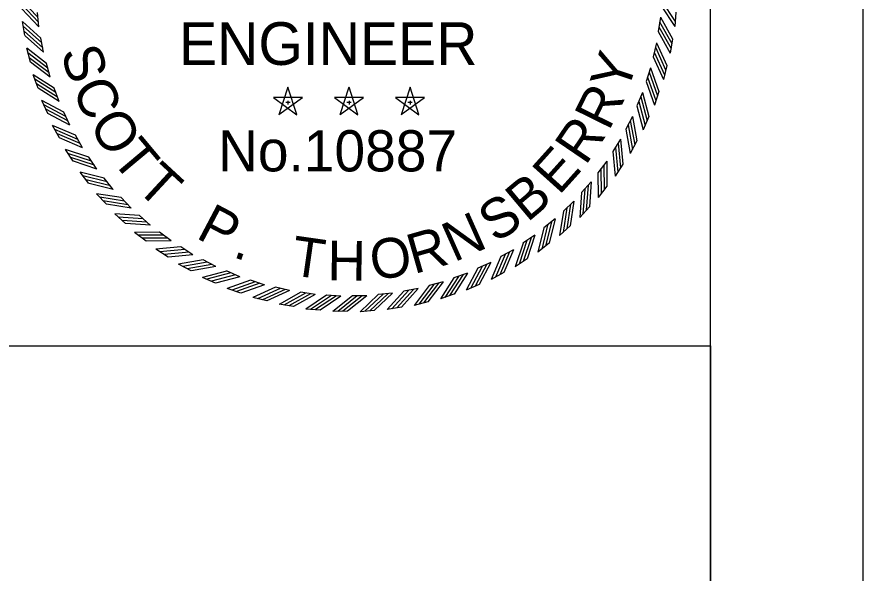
# Model space of a CAD drawing. Extents: x 0 to 1228740, y 0 to 152440.
# Drawn here: x 30.801 to 34, y 16.545 to 18.649 of the extents above; entities that cross this region are included whole.
import ezdxf

# ---------------------------------------------------------------- set-up
doc = ezdxf.new("R2010")
doc.units = 0
for name, color, linetype in [('R_Border', 7, 'Continuous'), ('R_No Plot', 7, 'Continuous'), ('STAMP', 7, 'Continuous')]:
    doc.layers.add(name, color=color, linetype=linetype)

msp = doc.modelspace()

# ---------------------------------------------------------------- linework, layer by layer
at = {"layer": 'R_Border'}
msp.add_line((33.4231, 0.5768), (33.4231, 21.4232), dxfattribs=at)
msp.add_lwpolyline([(33.9999, 22), (0, 22), (0, 0), (33.9999, 0)], close=True, dxfattribs=at)
at = {"layer": 'R_No Plot'}
for points in [[(33.4231, 17.4052), (33.4231, 10.8708), (1.516, 10.8708), (1.516, 21.4232), (25.1971, 21.4232), (25.1971, 20.4352), (28.7491, 20.4352), (28.7491, 20.0782), (29.1131, 20.0782), (29.1131, 20.1432), (30.6665, 20.1432)], [(30.6665, 20.1432), (30.6665, 17.4052), (33.4231, 17.4052)]]:
    msp.add_lwpolyline(points, dxfattribs=at)
at = {"layer": 'STAMP'}
for p, q in [((30.8837, 18.6117), (30.8787, 18.666)), ((33.2925, 18.6677), (33.2885, 18.6135)), ((30.8314, 18.5785), (30.822, 18.6321)), ((33.2337, 18.6484), (33.2252, 18.5945)), ((30.9013, 18.5154), (30.8918, 18.5691)), ((33.2793, 18.566), (33.2708, 18.5123)), ((30.8519, 18.478), (30.8381, 18.5306)), ((33.2191, 18.5516), (33.2062, 18.4986)), ((30.9268, 18.4209), (30.9129, 18.4737)), ((33.2577, 18.4657), (33.2449, 18.4129)), ((30.8807, 18.3796), (30.8626, 18.4309)), ((33.1965, 18.4563), (33.1793, 18.4046)), ((30.96, 18.3289), (30.9419, 18.3803)), ((31.8255, 18.384), (31.7915, 18.2795)), ((31.8594, 18.2796), (31.8256, 18.3841)), ((32.0563, 18.384), (32.0222, 18.2795)), ((32.0902, 18.2796), (32.0564, 18.3841)), ((32.2871, 18.384), (32.253, 18.2795)), ((32.321, 18.2796), (32.2871, 18.3841)), ((33.1662, 18.3633), (33.1447, 18.3131)), ((33.228, 18.3676), (33.2108, 18.316)), ((30.9175, 18.2838), (30.8952, 18.3335)), ((31.8804, 18.3441), (31.7705, 18.3442)), ((31.7706, 18.3441), (31.8594, 18.2795)), ((31.7916, 18.2796), (31.8805, 18.3441)), ((31.8256, 18.3324), (31.8256, 18.3186)), ((32.1112, 18.3441), (32.0013, 18.3442)), ((32.0014, 18.3441), (32.0902, 18.2795)), ((32.0224, 18.2796), (32.1113, 18.3441)), ((32.0564, 18.3324), (32.0564, 18.3186)), ((32.3419, 18.3441), (32.2321, 18.3442)), ((32.2322, 18.3441), (32.321, 18.2795)), ((32.2532, 18.2796), (32.3421, 18.3441)), ((32.2872, 18.3324), (32.2872, 18.3186)), ((31.8177, 18.3266), (31.834, 18.3266)), ((32.0485, 18.3266), (32.0648, 18.3266)), ((32.2793, 18.3266), (32.2956, 18.3266)), ((31.0007, 18.2399), (30.9784, 18.2896)), ((33.1283, 18.273), (33.1027, 18.2248)), ((33.1902, 18.2722), (33.1688, 18.2222)), ((30.9621, 18.1915), (30.9357, 18.2391)), ((31.0487, 18.1545), (31.0223, 18.2022)), ((33.083, 18.1863), (33.0536, 18.1403)), ((33.1447, 18.1803), (33.1192, 18.1323)), ((31.0141, 18.1031), (30.9839, 18.1484)), ((31.1035, 18.0734), (31.0732, 18.1188)), ((33.0308, 18.1035), (32.9977, 18.0601)), ((33.0917, 18.0925), (33.0624, 18.0467)), ((31.0733, 18.0193), (31.0395, 18.062)), ((31.1648, 17.9971), (31.1309, 18.0399)), ((32.9719, 18.0253), (32.9353, 17.9849)), ((31.1392, 17.9407), (31.1019, 17.9804)), ((33.0317, 18.0093), (32.9987, 17.9661)), ((31.2322, 17.9262), (31.1949, 17.966)), ((32.9067, 17.9523), (32.8669, 17.915)), ((32.965, 17.9314), (32.9286, 17.8911)), ((31.2113, 17.8678), (31.1709, 17.9043)), ((31.3052, 17.861), (31.2648, 17.8976)), ((32.8357, 17.8849), (32.793, 17.851)), ((32.8922, 17.8593), (32.8525, 17.8221)), ((31.2892, 17.8012), (31.246, 17.8342)), ((31.3834, 17.8021), (31.34, 17.8352)), ((32.7595, 17.8236), (32.7141, 17.7933)), ((32.8136, 17.7934), (32.7709, 17.7596)), ((31.3724, 17.7411), (31.3266, 17.7705)), ((31.4661, 17.7499), (31.4202, 17.7793)), ((32.6784, 17.7688), (32.6306, 17.7424)), ((31.5529, 17.7046), (31.5047, 17.7301)), ((32.7298, 17.7342), (32.6845, 17.704)), ((31.4602, 17.6882), (31.4121, 17.7136)), ((32.593, 17.7208), (32.5433, 17.6985)), ((31.5521, 17.6427), (31.5021, 17.6641)), ((31.6432, 17.6667), (31.593, 17.6882)), ((32.504, 17.6801), (32.4526, 17.662)), ((32.6414, 17.6822), (32.5938, 17.6558)), ((31.7362, 17.6364), (31.6845, 17.6536)), ((32.4119, 17.6469), (32.3592, 17.633)), ((32.549, 17.6376), (32.4994, 17.6153)), ((31.6475, 17.6049), (31.5959, 17.6221)), ((31.8315, 17.6138), (31.7785, 17.6267)), ((31.9283, 17.5992), (31.8744, 17.6077)), ((32.0259, 17.5927), (31.9715, 17.5967)), ((32.2212, 17.6038), (32.1669, 17.5988)), ((32.3175, 17.6214), (32.2637, 17.6119)), ((32.4533, 17.6008), (32.402, 17.5827)), ((31.7456, 17.5751), (31.6928, 17.588)), ((32.1238, 17.5942), (32.0692, 17.5937)), ((32.3549, 17.572), (32.3023, 17.5582)), ((31.8459, 17.5536), (31.7922, 17.5621)), ((31.9476, 17.5404), (31.8934, 17.5444)), ((32.0501, 17.5356), (31.9957, 17.5351)), ((32.1526, 17.5393), (32.0984, 17.5343)), ((32.2544, 17.5515), (32.2008, 17.5421))]:
    msp.add_line(p, q, dxfattribs=at)
for points in [[(30.8802, 18.6479), (30.8157, 18.7165)], [(30.8823, 18.6291), (30.8178, 18.6977)], [(33.2363, 18.6917), (33.2885, 18.6134)], [(33.2378, 18.7098), (33.29, 18.6315)], [(30.8838, 18.6117), (30.8193, 18.6803)], [(30.8918, 18.5691), (30.8219, 18.6321)], [(33.2307, 18.6312), (33.2764, 18.5488)], [(33.2336, 18.6484), (33.2793, 18.5661)], [(30.8948, 18.5512), (30.8249, 18.6142)], [(30.8985, 18.5327), (30.8286, 18.5957)], [(33.2252, 18.5945), (33.2709, 18.5122)], [(33.2282, 18.6124), (33.2739, 18.5301)], [(30.9014, 18.5154), (30.8315, 18.5784)], [(30.9129, 18.4736), (30.838, 18.5307)], [(33.2147, 18.5347), (33.2534, 18.4489)], [(33.219, 18.5517), (33.2577, 18.4658)], [(30.9174, 18.456), (30.8425, 18.5131)], [(30.9226, 18.4379), (30.8477, 18.4949)], [(33.2062, 18.4986), (33.2449, 18.4128)], [(33.2107, 18.5162), (33.2493, 18.4304)], [(30.9269, 18.4209), (30.852, 18.478)], [(30.9418, 18.3802), (30.8625, 18.4309)], [(33.1908, 18.4398), (33.2223, 18.3511)], [(33.1965, 18.4564), (33.228, 18.3677)], [(30.9477, 18.3631), (30.8684, 18.4138)], [(30.9544, 18.3454), (30.8751, 18.3961)], [(33.1793, 18.4046), (33.2108, 18.3159)], [(33.1852, 18.4218), (33.2167, 18.3331)], [(30.9601, 18.3288), (30.8808, 18.3795)], [(33.1662, 18.3634), (33.1902, 18.2723)], [(30.9784, 18.2895), (30.8951, 18.3335)], [(33.1591, 18.3473), (33.1832, 18.2563)], [(30.9857, 18.2729), (30.9024, 18.3169)], [(30.9938, 18.2559), (30.9105, 18.2998)], [(33.1448, 18.3132), (33.1688, 18.2222)], [(33.1521, 18.3298), (33.1761, 18.2388)], [(31.0008, 18.2398), (30.9176, 18.2838)], [(33.1282, 18.2731), (33.1447, 18.1804)], [(31.0223, 18.2022), (30.9357, 18.2391)], [(33.1114, 18.2408), (33.1279, 18.1481)], [(33.1199, 18.2577), (33.1364, 18.165)], [(31.0309, 18.1862), (30.9443, 18.2232)], [(31.0404, 18.1699), (30.9538, 18.2068)], [(33.1028, 18.2249), (33.1193, 18.1322)], [(31.0487, 18.1545), (30.9621, 18.1914)], [(33.0734, 18.1717), (33.0822, 18.0779)], [(33.083, 18.1863), (33.0917, 18.0926)], [(31.0732, 18.1187), (30.9839, 18.1484)], [(33.0537, 18.1404), (33.0624, 18.0466)], [(33.0636, 18.1555), (33.0723, 18.0618)], [(31.0831, 18.1036), (30.9938, 18.1332)], [(31.094, 18.0881), (31.0046, 18.1177)], [(31.1035, 18.0734), (31.0142, 18.1031)], [(33.02, 18.0898), (33.021, 17.9956)], [(33.0308, 18.1036), (33.0317, 18.0094)], [(31.1309, 18.0398), (31.0394, 18.062)], [(31.142, 18.0255), (31.0505, 18.0477)], [(32.9977, 18.0602), (32.9987, 17.966)], [(33.0089, 18.0745), (33.0098, 17.9803)], [(31.1541, 18.0109), (31.0626, 18.0331)], [(31.1649, 17.9971), (31.0734, 18.0193)], [(32.96, 18.0125), (32.9532, 17.9186)], [(32.9719, 18.0254), (32.9651, 17.9315)], [(31.1949, 17.9659), (31.1019, 17.9804)], [(32.9354, 17.9849), (32.9286, 17.891)], [(32.9477, 17.9982), (32.9408, 17.9043)], [(31.2072, 17.9526), (31.1142, 17.9671)], [(31.2204, 17.939), (31.1274, 17.9536)], [(32.9067, 17.9524), (32.8922, 17.8594)], [(31.2323, 17.9262), (31.1393, 17.9407)], [(32.867, 17.915), (32.8525, 17.822)], [(32.8803, 17.9273), (32.8658, 17.8343)], [(32.8938, 17.9405), (32.8793, 17.8475)], [(31.2648, 17.8975), (31.1709, 17.9043)], [(31.2781, 17.8852), (31.1842, 17.8921)], [(32.8358, 17.885), (32.8136, 17.7935)], [(31.2924, 17.8729), (31.1985, 17.8797)], [(31.3053, 17.861), (31.2114, 17.8678)], [(32.7931, 17.851), (32.7709, 17.7595)], [(32.8074, 17.8621), (32.7852, 17.7706)], [(32.8219, 17.8742), (32.7998, 17.7827)], [(31.3401, 17.8351), (31.2459, 17.8342)], [(31.3544, 17.824), (31.2602, 17.8231)], [(32.7595, 17.8237), (32.7298, 17.7343)], [(31.3696, 17.8129), (31.2755, 17.8119)], [(31.3835, 17.8021), (31.2893, 17.8012)], [(32.7142, 17.7933), (32.6845, 17.704)], [(32.7293, 17.8032), (32.6997, 17.7139)], [(32.7448, 17.8141), (32.7152, 17.7247)], [(31.4203, 17.7792), (31.3265, 17.7705)], [(31.4354, 17.7693), (31.3417, 17.7606)], [(31.4516, 17.7595), (31.3578, 17.7507)], [(32.663, 17.7605), (32.6261, 17.6739)], [(32.6784, 17.7688), (32.6415, 17.6823)], [(31.4662, 17.7499), (31.3725, 17.7411)], [(31.5048, 17.7301), (31.4121, 17.7136)], [(32.6307, 17.7424), (32.5938, 17.6558)], [(32.6467, 17.751), (32.6097, 17.6644)], [(31.5207, 17.7215), (31.428, 17.705)], [(31.5376, 17.713), (31.4449, 17.6965)], [(31.553, 17.7046), (31.4603, 17.6882)], [(32.5434, 17.6985), (32.4994, 17.6152)], [(32.56, 17.7058), (32.516, 17.6225)], [(32.577, 17.7139), (32.5331, 17.6306)], [(32.5931, 17.7209), (32.5491, 17.6377)], [(31.5931, 17.6881), (31.5021, 17.6641)], [(31.6097, 17.6808), (31.5187, 17.6568)], [(31.6272, 17.6738), (31.5362, 17.6497)], [(31.6433, 17.6667), (31.5522, 17.6427)], [(32.4527, 17.6619), (32.402, 17.5826)], [(32.4698, 17.6678), (32.4191, 17.5885)], [(32.4875, 17.6745), (32.4368, 17.5952)], [(32.5041, 17.6802), (32.4534, 17.6009)], [(31.6845, 17.6536), (31.5958, 17.6221)], [(31.7017, 17.6477), (31.613, 17.6162)], [(31.7197, 17.6421), (31.631, 17.6106)], [(31.7363, 17.6364), (31.6476, 17.6049)], [(32.3593, 17.633), (32.3022, 17.5581)], [(32.3768, 17.6375), (32.3198, 17.5626)], [(32.395, 17.6427), (32.338, 17.5678)], [(32.412, 17.647), (32.3549, 17.5721)], [(31.7785, 17.6267), (31.6927, 17.588)], [(31.7961, 17.6222), (31.7103, 17.5835)], [(31.8146, 17.6182), (31.7288, 17.5795)], [(31.8315, 17.6139), (31.7457, 17.5752)], [(31.8744, 17.6077), (31.7921, 17.562)], [(31.8923, 17.6047), (31.81, 17.559)], [(31.9111, 17.6022), (31.8287, 17.5565)], [(31.9283, 17.5993), (31.846, 17.5536)], [(31.9716, 17.5966), (31.8933, 17.5443)], [(31.9896, 17.5951), (31.9114, 17.5428)], [(32.1669, 17.5988), (32.0983, 17.5343)], [(32.185, 17.6003), (32.1164, 17.5358)], [(32.2038, 17.6024), (32.1352, 17.538)], [(32.2212, 17.6039), (32.1526, 17.5394)], [(32.2638, 17.6119), (32.2008, 17.542)], [(32.2817, 17.6149), (32.2186, 17.545)], [(32.3002, 17.6186), (32.2372, 17.5487)], [(32.3175, 17.6215), (32.2545, 17.5516)], [(32.0085, 17.5942), (31.9302, 17.5419)], [(32.026, 17.5927), (31.9477, 17.5404)], [(32.0693, 17.5937), (31.9956, 17.5351)], [(32.0874, 17.5937), (32.0137, 17.5351)], [(32.1063, 17.5943), (32.0326, 17.5357)], [(32.1238, 17.5943), (32.0501, 17.5357)]]:
    msp.add_lwpolyline(points, dxfattribs=at)

# ---------------------------------------------------------------- texts
for s, height, p in [('ENGINEER', 0.16155, (31.4137, 18.4677)), ('No.10887', 0.15578, (31.5614, 18.0649))]:
    msp.add_text(s, height=height, dxfattribs=at).set_placement(p)
for s, rotation, p in [('S', 286.9475, (30.9653, 18.5171)), ('Y', 71.7733, (33.1072, 18.3567)), ('C', 294.2435, (31.0071, 18.3799)), ('R', 63.7477, (33.0384, 18.2148)), ('O', 301.9044, (31.0694, 18.2429)), ('R', 55.7221, (32.9504, 18.084)), ('T', 309.93, (31.1536, 18.1096)), ('E', 48.0613, (32.8502, 17.9717)), ('T', 317.226, (31.2456, 17.9997)), ('B', 40.0357, (32.7301, 17.8695)), ('S', 32.7397, (32.6095, 17.7919)), ('P', 332.1828, (31.4737, 17.8153)), ('N', 23.9845, (32.4533, 17.72)), ('T', 351.882, (31.832, 17.6734)), ('R', 15.9589, (32.302, 17.6757)), ('H', 359.178, (31.974, 17.6531)), ('O', 7.9332, (32.146, 17.6529)), ('.', 340.2084, (31.6136, 17.7427))]:
    msp.add_text(s, height=0.1503, rotation=rotation, dxfattribs=at).set_placement(p)

doc.saveas('drawing.dxf')
